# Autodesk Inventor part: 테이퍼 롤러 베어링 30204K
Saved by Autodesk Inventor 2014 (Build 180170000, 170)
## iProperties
Created: 2026-05
Part Number: 테이퍼 롤러 베어링 30204K
Material: 일반
Document SubType Name: Modeling
Designer: dg
Density: 1 g/cm^3
Appearance: 기본값
Author: dg
Author: jhkim
Description: 테이퍼 롤러 베어링
Creation Date: 2026-04-23
Sending System: Autodesk Inventor 2027
Preprocessor: ST-DEVELOPER v20.1
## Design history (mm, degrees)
node "테이퍼 롤러 베어링 30204K1"
body "Solid1"
node "Solid1_1"
node "기준1"
node "기준2"
